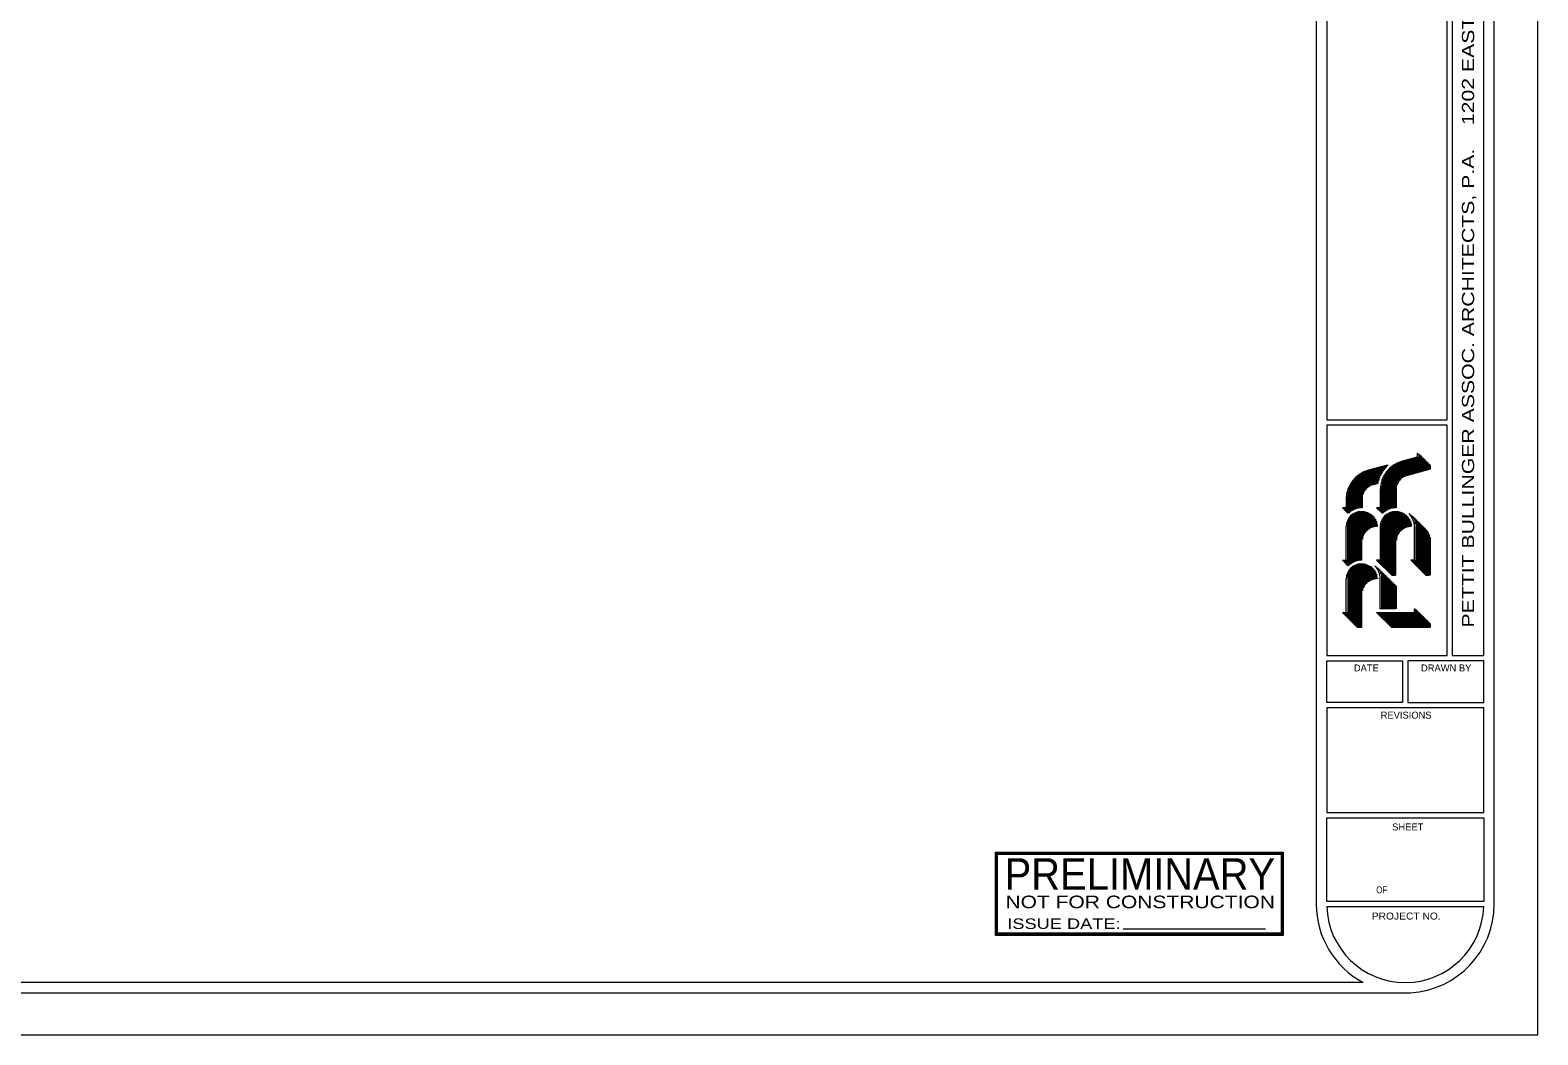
# Model space of a CAD drawing. Extents: x 0 to 144, y 0 to 96.
# Drawn here: x 72 to 144, y 0 to 48 of the extents above; entities that cross this region are included whole.
import ezdxf
from ezdxf.enums import TextEntityAlignment as Align

# ---------------------------------------------------------------- set-up
doc = ezdxf.new("R2010")
doc.units = 0
doc.header["$LTSCALE"] = 0.13
for name, color, linetype, lineweight in [('1', 7, 'Continuous', 13), ('61', 7, 'Continuous', 13), ('63', 7, 'Continuous', 13)]:
    doc.layers.add(name, color=color, linetype=linetype, lineweight=lineweight)

msp = doc.modelspace()

# ---------------------------------------------------------------- linework, layer by layer
at = {"layer": '1'}
for p, q in [((139.9137, 84.7524), (139.9137, 18.125)), ((133.4167, 81.7508), (133.4167, 6.25)), ((133.9167, 81.7508), (133.9167, 29.375)), ((141.9167, 6.25), (141.9167, 81.7508)), ((137.4489, 27.3717), (137.4489, 26.5351)), ((137.4906, 27.3868), (137.4906, 26.5742)), ((137.5322, 27.4004), (137.5322, 26.6077)), ((137.5739, 27.4128), (137.5739, 26.6365)), ((137.6156, 27.4241), (137.6156, 26.6612)), ((137.6572, 27.4354), (137.6572, 26.6825)), ((137.6989, 27.4467), (137.6989, 26.7005)), ((137.7406, 27.4581), (137.7406, 26.7155)), ((137.7822, 27.4694), (137.7822, 26.7278)), ((137.8239, 27.4807), (137.8239, 26.7392)), ((137.8656, 27.492), (137.8656, 26.7505)), ((137.9072, 27.5033), (137.9072, 26.7618)), ((137.9489, 27.5146), (137.9489, 26.7731)), ((137.9906, 27.526), (137.9906, 26.7844)), ((138.0322, 27.5373), (138.0322, 26.7957)), ((138.0739, 27.5486), (138.0739, 26.8071)), ((138.1156, 27.5599), (138.1156, 26.8184)), ((138.1572, 27.5712), (138.1572, 26.8297)), ((138.1989, 27.5825), (138.1989, 26.841)), ((138.2406, 27.5938), (138.2406, 26.8523)), ((138.2822, 27.6052), (138.2822, 26.8636)), ((138.3239, 27.7535), (138.3239, 26.8749)), ((138.3656, 27.7124), (138.3656, 26.8863)), ((138.4072, 27.6714), (138.4072, 26.8976)), ((138.4489, 27.6303), (138.4489, 26.9089)), ((138.4906, 27.5892), (138.4906, 26.9202)), ((138.5322, 27.5481), (138.5322, 26.9315)), ((138.5739, 27.507), (138.5739, 26.9428)), ((138.6156, 27.4659), (138.6156, 26.9542)), ((138.6572, 27.4248), (138.6572, 26.9655)), ((138.6989, 27.3837), (138.6989, 26.9768)), ((135.362, 26.6515), (135.362, 25.1427)), ((135.4036, 26.6874), (135.4036, 25.1536)), ((135.4453, 26.7208), (135.4453, 25.1623)), ((135.487, 26.7517), (135.487, 25.169)), ((135.5286, 26.7804), (135.5286, 25.1738)), ((135.5703, 26.8071), (135.5703, 25.1767)), ((135.612, 26.8318), (135.612, 25.1777)), ((135.6536, 26.8546), (135.6536, 25.8301)), ((135.6953, 26.8758), (135.6953, 25.925)), ((135.737, 26.8953), (135.737, 25.9939)), ((135.7786, 26.9132), (135.7786, 26.0489)), ((135.8203, 26.9297), (135.8203, 26.0946)), ((135.862, 26.9447), (135.862, 26.1333)), ((135.9036, 26.9583), (135.9036, 26.1665)), ((136.8219, 27.2199), (135.9113, 26.9726)), ((135.9453, 26.9705), (135.9453, 26.1951)), ((135.987, 26.9818), (135.987, 26.2196)), ((136.0286, 26.9931), (136.0286, 26.2407)), ((136.0703, 27.0045), (136.0703, 26.2585)), ((136.112, 27.0158), (136.112, 26.2734)), ((136.1536, 27.0271), (136.1536, 26.2856)), ((136.1953, 27.0384), (136.1953, 26.2969)), ((136.237, 27.0497), (136.237, 26.3082)), ((136.2786, 27.061), (136.2786, 26.3195)), ((136.3203, 27.0724), (136.3203, 26.3308)), ((136.362, 27.0837), (136.362, 26.3421)), ((136.4036, 27.095), (136.4036, 26.4892)), ((136.4453, 27.1063), (136.4453, 26.6111)), ((136.487, 27.1176), (136.487, 26.7089)), ((136.5286, 27.1289), (136.5286, 26.7919)), ((136.5703, 27.1402), (136.5703, 26.8646)), ((136.612, 27.1516), (136.612, 26.9295)), ((136.6536, 27.1629), (136.6536, 26.9883)), ((136.6572, 26.6461), (136.6572, 24.965)), ((136.6953, 27.1742), (136.6953, 27.0419)), ((136.6989, 26.7266), (136.6989, 24.9979)), ((136.737, 27.1855), (136.737, 27.0912)), ((136.7406, 26.7965), (136.7406, 25.0271)), ((136.7786, 27.1968), (136.7786, 27.1368)), ((136.7822, 26.8584), (136.7822, 25.053)), ((136.8203, 27.2081), (136.8203, 27.1791)), ((136.8239, 26.9141), (136.8239, 25.0759)), ((136.862, 27.2195), (136.862, 27.2184)), ((136.8656, 26.9646), (136.8656, 25.0961)), ((136.9072, 27.0107), (136.9072, 25.1137)), ((136.9489, 27.0531), (136.9489, 25.129)), ((136.9906, 27.0922), (136.9906, 25.1421)), ((137.0322, 27.1284), (137.0322, 25.153)), ((137.0739, 27.1619), (137.0739, 25.1618)), ((137.1156, 27.1929), (137.1156, 25.1687)), ((137.1572, 27.2218), (137.1572, 25.1736)), ((137.1989, 27.2485), (137.1989, 25.1766)), ((137.2406, 27.2733), (137.2406, 25.1777)), ((137.2822, 27.2963), (137.2822, 26.2661)), ((137.3239, 27.3176), (137.3239, 26.3633)), ((137.3656, 27.3372), (137.3656, 26.4333)), ((137.4072, 27.3552), (137.4072, 26.4889)), ((138.7406, 27.3426), (138.7406, 26.9881)), ((138.7822, 27.3015), (138.7822, 26.9994)), ((138.8239, 27.2604), (138.8239, 27.0107)), ((138.8656, 27.2193), (138.8656, 27.022)), ((134.9453, 25.9918), (134.9453, 24.9426)), ((134.987, 26.1131), (134.987, 24.9302)), ((135.0286, 26.2082), (135.0286, 24.9671)), ((135.0703, 26.288), (135.0703, 24.9997)), ((135.112, 26.3574), (135.112, 25.0287)), ((135.1536, 26.4189), (135.1536, 25.0544)), ((135.1953, 26.4742), (135.1953, 25.0771)), ((135.237, 26.5244), (135.237, 25.0971)), ((135.2786, 26.5703), (135.2786, 25.1147)), ((135.3203, 26.6125), (135.3203, 25.1298)), ((136.1038, 26.2833), (136.3261, 26.3437)), ((136.5322, 26.2289), (136.5322, 24.9861)), ((136.5739, 26.4263), (136.5739, 24.945)), ((136.6156, 26.5498), (136.6156, 24.9279)), ((137.2023, 25.1777), (137.2023, 26.037)), ((134.9036, 25.8029), (134.9036, 24.9837)), ((135.5713, 25.1777), (135.5713, 25.5941)), ((134.737, 25.1777), (134.737, 25.148)), ((134.7786, 25.1777), (134.7786, 25.1069)), ((134.8203, 25.1777), (134.8203, 25.0659)), ((134.862, 25.1777), (134.862, 25.0248)), ((134.9551, 24.5844), (134.9551, 22.4306)), ((134.9968, 24.6607), (134.9968, 22.4371)), ((135.0385, 24.72), (135.0385, 22.4729)), ((135.0801, 24.7688), (135.0801, 22.5046)), ((135.1218, 24.8099), (135.1218, 22.5328)), ((135.1635, 24.8449), (135.1635, 22.5578)), ((135.2051, 24.8751), (135.2051, 22.5799)), ((135.2468, 24.9011), (135.2468, 22.5993)), ((135.2885, 24.9234), (135.2885, 22.6162)), ((135.3301, 24.9423), (135.3301, 22.6308)), ((135.3718, 24.9583), (135.3718, 22.6433)), ((135.4135, 24.9714), (135.4135, 22.6536)), ((135.4551, 24.9818), (135.4551, 22.6618)), ((135.4968, 24.9898), (135.4968, 22.6681)), ((135.5385, 24.9952), (135.5385, 22.6725)), ((135.5801, 24.9983), (135.5801, 22.6749)), ((135.6218, 24.9989), (135.6218, 23.6804)), ((135.6635, 24.9973), (135.6635, 23.8313)), ((135.7051, 24.9932), (135.7051, 23.918)), ((135.7468, 24.9867), (135.7468, 23.983)), ((135.7885, 24.9777), (135.7885, 24.0355)), ((135.8301, 24.9662), (135.8301, 24.0794)), ((135.8718, 24.9519), (135.8718, 24.1167)), ((135.9135, 24.9347), (135.9135, 24.1487)), ((135.9551, 24.9143), (135.9551, 24.1763)), ((135.9968, 24.8906), (135.9968, 24.2)), ((136.0385, 24.8629), (136.0385, 24.2202)), ((136.0801, 24.8307), (136.0801, 24.2374)), ((136.1218, 24.7933), (136.1218, 24.2516)), ((136.1635, 24.7492), (136.1635, 24.2631)), ((136.2051, 24.6964), (136.2051, 24.272)), ((136.2468, 24.631), (136.2468, 24.2784)), ((136.2885, 24.5435), (136.2885, 24.2824)), ((136.3656, 25.1777), (136.3656, 25.1504)), ((136.4072, 25.1777), (136.4072, 25.1093)), ((136.4489, 25.1777), (136.4489, 25.0682)), ((136.4906, 25.1777), (136.4906, 25.0272)), ((136.5801, 24.5712), (136.5801, 22.4366)), ((136.6218, 24.6509), (136.6218, 22.3955)), ((136.6635, 24.7122), (136.6635, 22.3544)), ((136.7051, 24.7623), (136.7051, 22.3133)), ((136.7468, 24.8043), (136.7468, 22.2722)), ((136.7885, 24.8402), (136.7885, 22.2311)), ((136.8301, 24.871), (136.8301, 22.19)), ((136.8718, 24.8976), (136.8718, 22.1489)), ((136.9135, 24.9204), (136.9135, 22.1078)), ((136.9551, 24.9398), (136.9551, 22.0667)), ((136.9968, 24.9561), (136.9968, 22.0256)), ((137.0385, 24.9697), (137.0385, 21.9845)), ((137.0801, 24.9805), (137.0801, 21.9606)), ((137.1218, 24.9888), (137.1218, 21.9606)), ((137.1635, 24.9946), (137.1635, 21.9606)), ((137.2051, 24.998), (137.2051, 21.9606)), ((137.2468, 24.999), (137.2468, 23.6321)), ((137.2885, 24.9976), (137.2885, 23.8157)), ((137.3301, 24.9939), (137.3301, 23.9072)), ((137.3718, 24.9878), (137.3718, 23.9746)), ((137.4135, 24.9792), (137.4135, 24.0286)), ((137.4551, 24.968), (137.4551, 24.0735)), ((137.4968, 24.9541), (137.4968, 24.1117)), ((137.5385, 24.9373), (137.5385, 24.1444)), ((137.5801, 24.9175), (137.5801, 24.1726)), ((137.6218, 24.8942), (137.6218, 24.1968)), ((137.6635, 24.8671), (137.6635, 24.2175)), ((137.7051, 24.8357), (137.7051, 24.2351)), ((137.7468, 24.799), (137.7468, 24.2497)), ((137.7885, 24.756), (137.7885, 24.2616)), ((137.8301, 24.7047), (137.8301, 24.2709)), ((137.8438, 24.9152), (138.5679, 24.2011)), ((138.5679, 24.2011), (137.8438, 24.9152)), ((137.8718, 24.6415), (137.8718, 24.2776)), ((137.8934, 24.9074), (137.8934, 24.9073)), ((137.9135, 24.5582), (137.9135, 24.282)), ((137.9351, 24.8663), (137.9351, 24.8621)), ((137.9767, 24.8252), (137.9767, 24.8098)), ((138.0184, 24.7841), (138.0184, 24.748)), ((138.0601, 24.743), (138.0601, 24.6724)), ((138.1017, 24.7019), (138.1017, 24.5721)), ((138.1434, 24.6608), (138.1434, 24.3925)), ((138.1851, 24.6197), (138.1851, 22.4623)), ((138.2267, 24.5786), (138.2267, 22.4212)), ((138.2684, 24.5376), (138.2684, 22.3801)), ((138.3101, 24.4965), (138.3101, 22.339)), ((134.9135, 24.4716), (134.9135, 22.4717)), ((136.3301, 24.3882), (136.3301, 24.284)), ((136.5385, 24.4483), (136.5385, 22.4777)), ((137.9551, 24.4226), (137.9551, 24.2839)), ((138.3517, 24.4554), (138.3517, 22.2979)), ((138.3934, 24.4143), (138.3934, 22.2568)), ((138.4351, 24.3732), (138.4351, 22.2157)), ((138.4767, 24.3321), (138.4767, 22.1746)), ((138.5184, 24.291), (138.5184, 22.1335)), ((138.5601, 24.2499), (138.5601, 22.0924)), ((138.6017, 24.2088), (138.6017, 22.0513)), ((138.6434, 24.1658), (138.6434, 22.0102)), ((138.6851, 24.1166), (138.6851, 21.9691)), ((138.7267, 24.059), (138.7267, 21.9606)), ((138.7684, 23.9897), (138.7684, 21.9606)), ((138.8101, 23.9013), (138.8101, 21.9606)), ((138.8517, 23.7703), (138.8517, 21.9606)), ((135.5713, 23.5691), (135.5713, 22.6755)), ((134.7468, 22.6755), (134.7468, 22.6361)), ((134.7885, 22.6755), (134.7885, 22.595)), ((134.8301, 22.6755), (134.8301, 22.5539)), ((134.8718, 22.6755), (134.8718, 22.5128)), ((135.1697, 22.3475), (135.1697, 19.7168)), ((135.2114, 22.377), (135.2114, 19.6757)), ((135.2531, 22.4024), (135.2531, 19.6346)), ((135.2947, 22.4242), (135.2947, 19.5935)), ((135.3364, 22.4427), (135.3364, 19.5524)), ((135.3781, 22.4582), (135.3781, 19.5113)), ((135.4197, 22.4709), (135.4197, 19.4702)), ((135.4614, 22.481), (135.4614, 19.4583)), ((135.5031, 22.4885), (135.5031, 19.4583)), ((135.5447, 22.4936), (135.5447, 19.4583)), ((135.5864, 22.4963), (135.5864, 19.4583)), ((135.6281, 22.4966), (135.6281, 21.2121)), ((135.6697, 22.4946), (135.6697, 21.3442)), ((135.7114, 22.4901), (135.7114, 21.4266)), ((135.7531, 22.4833), (135.7531, 21.4894)), ((135.7947, 22.4739), (135.7947, 21.5404)), ((135.8364, 22.462), (135.8364, 21.5832)), ((135.8781, 22.4472), (135.8781, 21.6196)), ((135.9197, 22.4296), (135.9197, 21.6509)), ((135.9614, 22.4088), (135.9614, 21.6779)), ((136.0031, 22.3844), (136.0031, 21.701)), ((136.0447, 22.3561), (136.0447, 21.7208)), ((136.0864, 22.3232), (136.0864, 21.7374)), ((136.2128, 22.413), (137.2023, 21.4371)), ((136.2772, 22.3906), (136.2772, 22.3897)), ((136.3189, 22.3495), (136.3189, 22.3422)), ((136.3718, 22.6755), (136.3718, 22.642)), ((136.4135, 22.6755), (136.4135, 22.6009)), ((136.4551, 22.6755), (136.4551, 22.5598)), ((136.4968, 22.6755), (136.4968, 22.5188)), ((137.9767, 22.6755), (137.9767, 22.6677)), ((138.0184, 22.6755), (138.0184, 22.6266)), ((138.0601, 22.6755), (138.0601, 22.5856)), ((138.1017, 22.6755), (138.1017, 22.5445)), ((138.1434, 22.6755), (138.1434, 22.5034)), ((134.9197, 21.9908), (134.9197, 19.9633)), ((134.9614, 22.0952), (134.9614, 19.9222)), ((135.0031, 22.1682), (135.0031, 19.8811)), ((135.0447, 22.2257), (135.0447, 19.84)), ((135.0864, 22.2732), (135.0864, 19.7989)), ((135.1281, 22.3133), (135.1281, 19.7578)), ((136.1281, 22.2849), (136.1281, 21.7512)), ((136.1697, 22.2397), (136.1697, 21.7623)), ((136.2114, 22.1853), (136.2114, 21.7709)), ((136.2531, 22.1174), (136.2531, 21.7769)), ((136.2947, 22.0248), (136.2947, 21.7806)), ((136.3364, 21.8272), (136.3364, 21.7818)), ((136.3605, 22.3084), (136.3605, 22.2869)), ((136.4022, 22.2673), (136.4022, 22.2209)), ((136.4439, 22.2262), (136.4439, 22.1384)), ((136.4855, 22.1851), (136.4855, 22.0228)), ((136.5272, 22.144), (136.5272, 20.352)), ((136.5689, 22.1029), (136.5689, 20.352)), ((136.6105, 22.0618), (136.6105, 20.352)), ((136.6522, 22.0207), (136.6522, 20.352)), ((136.6939, 21.9796), (136.6939, 20.352)), ((136.7355, 21.9385), (136.7355, 20.352)), ((136.7772, 21.8974), (136.7772, 20.352)), ((136.8189, 21.8564), (136.8189, 20.352)), ((136.8605, 21.8153), (136.8605, 20.352)), ((136.9022, 21.7742), (136.9022, 20.352)), ((136.9439, 21.7331), (136.9439, 20.352)), ((136.9855, 21.692), (136.9855, 20.352)), ((137.0272, 21.6509), (137.0272, 20.352)), ((137.0689, 21.6098), (137.0689, 20.352)), ((137.1105, 21.5687), (137.1105, 20.352)), ((137.1522, 21.5276), (137.1522, 20.352)), ((137.1939, 21.4865), (137.1939, 20.352)), ((137.2355, 21.4454), (137.2355, 20.352)), ((134.7114, 20.1733), (134.7114, 20.1688)), ((134.7531, 20.1733), (134.7531, 20.1277)), ((134.7947, 20.1733), (134.7947, 20.0866)), ((134.8364, 20.1733), (134.8364, 20.0455)), ((134.8781, 20.1733), (134.8781, 20.0044)), ((136.3591, 20.1733), (136.3591, 20.1523)), ((136.4007, 20.1733), (136.4007, 20.1112)), ((136.4424, 20.1733), (136.4424, 20.0702)), ((136.4841, 20.1733), (136.4841, 20.0291)), ((136.5257, 20.1733), (136.5257, 19.988)), ((136.5674, 20.1733), (136.5674, 19.9469)), ((136.6091, 20.1733), (136.6091, 19.9058)), ((136.6507, 20.1733), (136.6507, 19.8647)), ((136.6924, 20.1733), (136.6924, 19.8236)), ((136.7341, 20.1733), (136.7341, 19.7825)), ((136.7757, 20.1733), (136.7757, 19.7414)), ((136.8174, 20.1733), (136.8174, 19.7003)), ((136.8591, 20.1733), (136.8591, 19.6592)), ((136.9007, 20.1733), (136.9007, 19.6181)), ((136.9424, 20.1733), (136.9424, 19.577)), ((136.9841, 20.1733), (136.9841, 19.5359)), ((137.0257, 20.1733), (137.0257, 19.4948)), ((137.0674, 20.1733), (137.0674, 19.4583)), ((137.1091, 20.1733), (137.1091, 19.4583)), ((137.1507, 20.1733), (137.1507, 19.4583)), ((137.1924, 20.1733), (137.1924, 19.4583)), ((137.2341, 20.1733), (137.2341, 19.4583)), ((137.2757, 20.1733), (137.2757, 19.4583)), ((137.3174, 20.1733), (137.3174, 19.4583)), ((137.3591, 20.1733), (137.3591, 19.4583)), ((137.4007, 20.1733), (137.4007, 19.4583)), ((137.4424, 20.1733), (137.4424, 19.4583)), ((137.4841, 20.1733), (137.4841, 19.4583)), ((137.5257, 20.1733), (137.5257, 19.4583)), ((137.5674, 20.1733), (137.5674, 19.4583)), ((137.6091, 20.1733), (137.6091, 19.4583)), ((137.6507, 20.1733), (137.6507, 19.4583)), ((137.6924, 20.1733), (137.6924, 19.4583)), ((137.7341, 20.1733), (137.7341, 19.4583)), ((137.7757, 20.1733), (137.7757, 19.4583)), ((137.8174, 20.1733), (137.8174, 19.4583)), ((137.8591, 20.1733), (137.8591, 19.4583)), ((137.9007, 20.1733), (137.9007, 19.4583)), ((137.9424, 20.1733), (137.9424, 19.4583)), ((137.9841, 20.1733), (137.9841, 19.4583)), ((138.0257, 20.1733), (138.0257, 19.4583)), ((138.0674, 20.1733), (138.0674, 19.4583)), ((138.1091, 20.1733), (138.1091, 19.4583)), ((138.1507, 20.3514), (138.1507, 19.4583)), ((138.1924, 20.3103), (138.1924, 19.4583)), ((138.2341, 20.2692), (138.2341, 19.4583)), ((138.2757, 20.2281), (138.2757, 19.4583)), ((138.3174, 20.187), (138.3174, 19.4583)), ((138.3591, 20.1459), (138.3591, 19.4583)), ((138.4007, 20.1048), (138.4007, 19.4583)), ((138.4424, 20.0637), (138.4424, 19.4583)), ((138.4841, 20.0226), (138.4841, 19.4583)), ((138.5257, 19.9815), (138.5257, 19.4583)), ((138.5674, 19.9404), (138.5674, 19.4583)), ((138.6091, 19.8993), (138.6091, 19.4583)), ((138.6507, 19.8582), (138.6507, 19.4583)), ((138.6924, 19.8171), (138.6924, 19.4583)), ((138.7341, 19.776), (138.7341, 19.4583)), ((138.7757, 19.7349), (138.7757, 19.4583)), ((138.8174, 19.6939), (138.8174, 19.4583)), ((138.8591, 19.6528), (138.8591, 19.4583)), ((133.9167, 18.125), (139.6667, 18.125)), ((133.9167, 17.875), (137.5417, 17.875)), ((137.5402, 17.875), (137.5402, 15.875)), ((137.7902, 17.875), (137.7902, 15.875)), ((141.4137, 17.875), (137.7917, 17.875)), ((141.4167, 15.875), (141.4167, 17.875)), ((137.7917, 15.875), (141.4137, 15.875)), ((141.4167, 10.625), (141.4167, 15.625)), ((133.9167, 10.625), (141.4137, 10.625)), ((133.9167, 10.375), (141.4137, 10.375)), ((133.9167, 6.125), (141.4137, 6.125)), ((135.6658, 2.5), (10.25, 2.5)), ((10.25, 2), (137.9167, 2))]:
    msp.add_line(p, q, dxfattribs=at)
for points in [[(133.9167, 29.375), (139.6637, 29.375), (139.6637, 84.9243)], [(139.9167, 18.125), (141.4167, 18.125), (141.4167, 81.7508)], [(139.6637, 18.125), (139.6637, 29.125), (133.9167, 29.125), (133.9167, 18.125)], [(137.7348, 26.7263), (138.8333, 27.0246), (138.8333, 27.21), (138.2438, 27.7914), (138.2438, 27.606), (137.5423, 27.4155)], [(136.4774, 26.037), (136.4774, 25.1777), (136.2962, 25.1777), (136.5616, 24.916)], [(134.8464, 25.5941), (134.8464, 25.1777), (134.6652, 25.1777), (134.9306, 24.916)], [(134.9306, 22.4138), (134.6652, 22.6755), (134.8464, 22.6755), (134.8464, 24.2841)], [(136.4774, 24.2841), (136.4774, 22.6755), (136.2962, 22.6755), (137.0211, 21.9606), (137.2023, 21.9606), (137.2023, 23.5691)], [(138.8333, 23.5691), (138.8333, 21.9606), (138.6521, 21.9606), (137.9272, 22.6755), (138.1084, 22.6755), (138.1084, 24.2841)], [(138.1084, 24.2841), (138.1084, 22.6755), (137.9272, 22.6755), (138.6521, 21.9606), (138.8333, 21.9606), (138.8333, 23.5691)], [(135.5713, 21.0669), (135.5713, 19.4583), (135.3901, 19.4583), (134.6652, 20.1733), (134.8464, 20.1733), (134.8464, 21.7818)], [(137.2023, 21.4371), (137.2023, 20.352), (136.4774, 20.352), (136.4774, 21.7818)], [(137.5417, 15.875), (133.9167, 15.875), (133.9167, 17.875)], [(141.4137, 15.625), (133.9167, 15.625), (133.9167, 10.625)], [(141.4167, 10.375), (141.4167, 6.375), (133.9167, 6.375), (133.9167, 10.375)]]:
    msp.add_lwpolyline(points, dxfattribs=at)
msp.add_lwpolyline([(138.8333, 19.4583), (137.0211, 19.4583), (136.2962, 20.1733), (138.1084, 20.1733), (138.1084, 20.352), (138.8333, 19.6371)], close=True, dxfattribs=at)
for radius, start, end in [(4.25, 180, 241.92751), (3.75, 181.90958, 358.08979), (4.25, 273.37766, 0)]:
    msp.add_arc((137.6658, 6.25), radius, start, end, dxfattribs=at)
for centre, major_axis, start_param, end_param in [((137.9272, 26.037), (-1.4498, 0), 4.9810939, 6.2831853), ((136.2962, 25.5941), (-1.4498, 0), 4.9810923, 6.2831853), ((137.9272, 26.037), (1.631, 0), 2.3153848, 2.949748), ((137.9272, 26.037), (-0.7249, 0), 4.9810954, 6.2831853), ((136.2962, 25.5941), (-0.7249, 0), 4.9810964, 6.2831853), ((135.5713, 24.2841), (-0.7249, 0), 3.1415927, 6.2831853), ((135.5713, 24.2841), (-0.9061, 0), 4.712389, 5.4977871), ((137.2023, 24.2841), (-0.7249, 0), 3.1415927, 6.2831853), ((137.2023, 24.2841), (-0.9061, 0), 4.712389, 5.4977871), ((137.2023, 24.2841), (-0.9061, 0), 3.1415927, 3.9257651), ((137.2023, 24.2841), (-0.9061, 0), 3.1415927, 3.9257651), ((136.2962, 23.5691), (-0.7249, 0), 4.712389, 6.2831853), ((137.9272, 23.5691), (-0.7249, 0), 4.712389, 6.2831853), ((137.9272, 23.5691), (0.9061, 0), 6.2831853, 7.0685835), ((135.5713, 21.7818), (-0.7249, 0), 3.1415927, 6.2831853), ((135.5713, 21.7818), (-0.9061, 0), 4.712389, 5.4977871), ((135.5713, 21.7818), (-0.9061, 0), 3.1415927, 3.9257651), ((136.2962, 21.0669), (-0.7249, 0), 4.712389, 6.2831853)]:
    msp.add_ellipse(centre, major_axis=major_axis, ratio=0.98625, start_param=start_param, end_param=end_param, dxfattribs=at)
at = {"layer": '61'}
msp.add_lwpolyline([(144, 96), (0, 96), (0, 0), (144, 0)], close=True, dxfattribs=at)
at = {"layer": '63'}
msp.add_line((124.2021, 5.0607), (130.9938, 5.0607), dxfattribs=at)
for points in [[(118.0938, 8.7274), (131.8438, 8.7274), (131.8438, 4.7524), (118.0938, 4.7524)], [(118.1437, 8.6774), (131.7937, 8.6774), (131.7937, 4.8024), (118.1437, 4.8024)], [(118.1937, 8.6274), (131.7438, 8.6274), (131.7438, 4.8524), (118.1937, 4.8524)]]:
    msp.add_lwpolyline(points, close=True, dxfattribs=at)

# ---------------------------------------------------------------- texts
at = {"layer": '1', "width": 1.3}
msp.add_text('PETTIT BULLINGER ASSOC. ARCHITECTS, P.A.    1202 EAST FIRST    P.O.BOX 2726    WICHITA, KANSAS  67201    (316) 262-7435', height=0.5833, rotation=90, dxfattribs=at).set_placement((140.9583, 19.4583))
at = {"layer": '1'}
for s, p in [('DATE', (135.2141, 17.3614)), ('DRAWN BY', (138.4223, 17.3614)), ('REVISIONS', (136.4962, 15.1078)), ('SHEET', (137.0461, 9.7656))]:
    msp.add_text(s, height=0.3333, dxfattribs=at).set_placement(p)
for s, width, p in [('OF', 0.85, (136.2834, 6.7608)), ('PROJECT NO.', 1.1, (136.067, 5.5088))]:
    msp.add_text(s, height=0.3333, dxfattribs=dict(at, width=width)).set_placement(p)
at = {"layer": '63'}
for s, height, width, p in [('PRELIMINARY', 1.5, 0.95, (124.9937, 6.9357)), ('NOT FOR CONSTRUCTION', 0.6, 1.25, (125.0101, 6.0524)), ('ISSUE DATE:', 0.5, 1.3, (121.3687, 5.0607))]:
    msp.add_text(s, height=height, dxfattribs=dict(at, width=width)).set_placement(p, align=Align.CENTER)

doc.saveas('drawing.dxf')
